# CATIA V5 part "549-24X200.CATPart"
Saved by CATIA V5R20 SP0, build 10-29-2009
Part number: 549-24X200
Definition: NONE
Nomenclature: 549-24X200
Source: Unknown
Description: 549-24X200
Bounding box of the stored display mesh (mm): x 0 to 200, y -13.5 to 13.5, z -13.5 to 13.5
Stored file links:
  C:\Users\Utente\Desktop\IO LAVORO\3D X SITO CF\X SITO\PLASTICA\549\549-24X200.CATPart
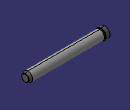
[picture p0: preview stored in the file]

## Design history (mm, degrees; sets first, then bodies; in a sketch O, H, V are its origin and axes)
Body1 "549-24X200" (main body)
  Solid1: solid without history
